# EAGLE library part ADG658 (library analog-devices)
+3 V/+5 V/±5 V CMOS 8-Channel Analog Multiplexers Source: ADG658_659.pdf
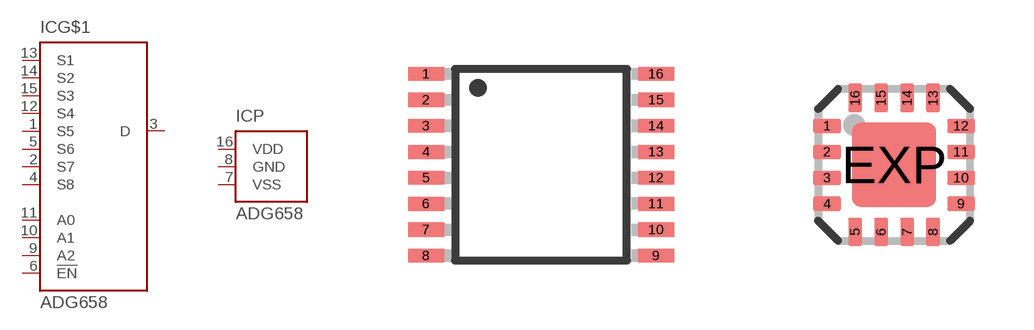
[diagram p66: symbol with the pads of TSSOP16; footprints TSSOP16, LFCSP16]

Designator prefix IC; gates P=PWR-VSS_GND_VDD G$1=ADG658

## ADG658RU (MPN: ADG658YRUZ; OC_FARNELL: 1438947; OC_NEWARK: 19M8665)  [TSSOP16]
1  G$1:S5
2  G$1:S7
3  G$1:D
4  G$1:S8
5  G$1:S6
6  G$1:!EN  in
7  P:VSS  pwr
8  P:GND  pwr
9  G$1:A2  in
10  G$1:A1  in
11  G$1:A0  in
12  G$1:S4
13  G$1:S1
14  G$1:S2
15  G$1:S3
16  P:VDD  pwr

## ADG658CP (MF: ALTERA CORPORATION; MPN: ADG658YCP; OC_FARNELL: unknown; OC_NEWARK: 87H9636)  [LFCSP16]
1  G$1:D
2  G$1:S8
3  G$1:S6
4  G$1:!EN  in
5  P:VSS  pwr
6  P:GND  pwr
7  G$1:A2  in
8  G$1:A1  in
9  G$1:A0  in
10  G$1:S4
11  G$1:S1
12  G$1:S2
13  G$1:S3
14  P:VDD  pwr
15  G$1:S5
16  G$1:S7

## ADG658RQ (MF: ALTERA CORPORATION; MPN: ADG658YRQ-REEL7; OC_FARNELL: 1438947; OC_NEWARK: 59K1455)  [QSOP16]
Pads as for TSSOP16

## Footprint TSSOP16 (pad centres in mm)
16-Lead Thin Shrink Small Outline Package [TSSOP] (RU-16) Source: 8x ADG1408_1409.pdf
smd 0.9 x 0.35: 1 -2.875,2.275; 2 -2.875,1.625; 3 -2.875,0.975; 4 -2.875,0.325; 5 -2.875,-0.325; 6 -2.875,-0.975; 7 -2.875,-1.625; 8 -2.875,-2.275; 9 2.875,-2.275; 10 2.875,-1.625; 11 2.875,-0.975; 12 2.875,-0.325; 13 2.875,0.325; 14 2.875,0.975; 15 2.875,1.625; 16 2.875,2.275

## Footprint LFCSP16 (pad centres in mm)
16-Terminal Leadless Frame Chip Scale Package [LFCSP] (CP) Source: Analog Devices .. 780914713ADD8704_0.pdf
smd 0.7 x 0.35: 1 -1.675,0.975; 2 -1.675,0.325; 3 -1.675,-0.325; 4 -1.675,-0.975; 9 1.675,-0.975; 10 1.675,-0.325; 11 1.675,0.325; 12 1.675,0.975
smd 0.35 x 0.7: 5 -0.975,-1.675; 6 -0.325,-1.675; 7 0.325,-1.675; 8 0.975,-1.675; 13 0.975,1.675; 14 0.325,1.675; 15 -0.325,1.675; 16 -0.975,1.675
smd 2.1 x 2.1: EXP 0,0

## Footprint QSOP16 (pad centres in mm)
16-Lead Shrink Small Outline Package QSOP (RQ-16) Source: ADG658_659.pdf
smd 0.381 x 1.27: 1 -2.223,-2.6; 2 -1.587,-2.6; 3 -0.953,-2.6; 4 -0.318,-2.6; 5 0.318,-2.6; 6 0.953,-2.6; 7 1.587,-2.6; 8 2.223,-2.6; 9 2.223,2.6; 10 1.587,2.6; 11 0.953,2.6; 12 0.318,2.6; 13 -0.318,2.6; 14 -0.953,2.6; 15 -1.587,2.6; 16 -2.223,2.6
